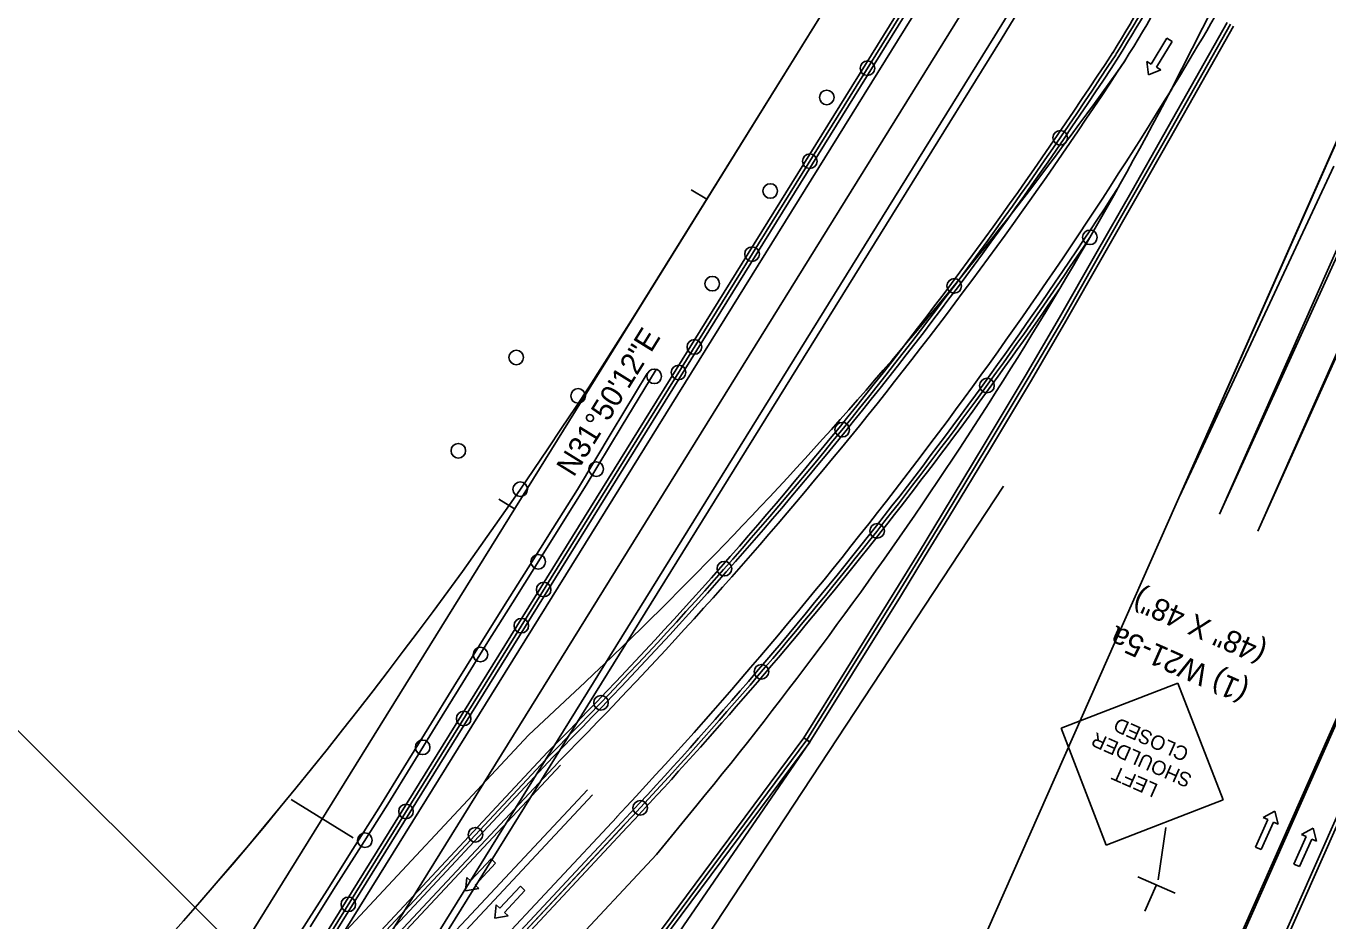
# Model space of a CAD drawing. Extents: x 659657 to 668193, y 633084 to 648639.
# Drawn here: x 662117 to 662474.2, y 643133.4 to 643378.9 of the extents above; entities that cross this region are included whole.
import ezdxf

# ---------------------------------------------------------------- set-up
doc = ezdxf.new("R2010")
doc.units = 0
for name, color, linetype in [('R_Border Prem', 7, 'Continuous'), ('R_Draft', 7, 'Continuous'), ('R_MOT_Stage 1', 7, 'Continuous'), ('R_MOT_Stage 1_Striping', 7, 'Continuous'), ('R_MOT_Stage 2', 7, 'Continuous'), ('R_MOT_Stage 2_Striping', 7, 'Continuous'), ('R_MOT_Stage 3', 7, 'Continuous'), ('R_MOT_Stage 3_Striping', 7, 'Continuous'), ('R_MOT_Stage 3_Striping_PPM', 7, 'Continuous'), ('R_MOT_Stage 4', 7, 'Continuous'), ('R_MOT_Stage 4_Striping', 7, 'Continuous'), ('R_MOT_Stage 4_Striping_PPM', 7, 'Continuous'), ('R_MOT_Stage 5_Striping_PPM', 7, 'Continuous'), ('R_ROW Annot', 7, 'Continuous'), ('S_EXISTING_ALIGNMENT', 7, 'Continuous'), ('T_Notes', 7, 'Continuous'), ('T_SIGNAL CONTROL CABINET', 7, 'Continuous'), ('TEMP_SIGNAL_POLES_STAGE 2', 7, 'Continuous')]:
    doc.layers.add(name, color=color, linetype=linetype)

msp = doc.modelspace()

# ---------------------------------------------------------------- linework, layer by layer
at = {"layer": 'R_Border Prem'}
msp.add_line((661686.79, 641562.92), (662861.91, 644217.67), dxfattribs=at)
at = {"layer": 'R_Draft'}
for p, q in [((662400.98, 643186.24), (662433.05, 643198.61)), ((662433.05, 643198.61), (662445.45, 643166.55)), ((662400.98, 643186.24), (662413.37, 643154.16)), ((662413.37, 643154.16), (662445.45, 643166.55)), ((662429.73, 643159.02), (662427.6, 643144.65)), ((662422.04, 643145.5), (662432.33, 643140.95)), ((662427.09, 643143.08), (662423.98, 643136.06))]:
    msp.add_line(p, q, dxfattribs=at)
at = {"layer": 'R_MOT_Stage 1'}
for centre in [(662336.72, 643359.32), (662321.21, 643333.64), (662305.3, 643308.21), (662289.38, 643282.78), (662273.46, 643257.35), (662257.54, 643231.92), (662241.69, 643206.45), (662225.83, 643180.99), (662209.98, 643155.52)]:
    msp.add_circle(centre, 2, dxfattribs=at)
at = {"layer": 'R_MOT_Stage 1_Striping'}
msp.add_line((662175.55, 643124.86), (662368.1, 643434.97), dxfattribs=at)
for points in [[(662299.52, 643334), (662303.77, 643331.36)], [(662175.55, 643124.86), (662034.06, 643266.21)], [(662246.77, 643249.05), (662251.02, 643246.41)], [(662189.77, 643166.73), (662206.77, 643156.18)]]:
    msp.add_lwpolyline(points, dxfattribs=at)
at = {"layer": 'R_MOT_Stage 2'}
for p, q in [((662183.21, 643104.02), (662360.74, 643389.94)), ((662184.91, 643102.96), (662362.44, 643388.89)), ((662206.99, 643089.25), (662384.53, 643375.17))]:
    msp.add_line(p, q, dxfattribs=at)
for centre in [(662347.86, 643367.31), (662332.04, 643341.82), (662316.21, 643316.33), (662300.39, 643290.85), (662251.51, 643287.96), (662296.04, 643283.85), (662268.5, 643277.41), (662235.62, 643262.37), (662252.61, 643251.82), (662259.05, 643224.28), (662252.91, 643214.39), (662237.09, 643188.9), (662221.26, 643163.41), (662205.44, 643137.93)]:
    msp.add_circle(centre, 2, dxfattribs=at)
msp.add_arc((661886.73, 643684.27), 585.96, 328.16324, 359.34796, dxfattribs=at)
at = {"layer": 'R_MOT_Stage 2_Striping'}
for p, q in [((662653.91, 643589.66), (661803.9, 641669.37)), ((661813.96, 641664.92), (662663.97, 643585.2)), ((662175.55, 643124.86), (662368.1, 643434.97)), ((662186.61, 643101.91), (662364.14, 643387.83)), ((662195.95, 643096.11), (662373.49, 643382.03)), ((662205.3, 643090.3), (662382.83, 643376.23))]:
    msp.add_line(p, q, dxfattribs=at)
for points in [[(662299.52, 643334), (662303.77, 643331.36)], [(662175.55, 643124.86), (662034.06, 643266.21)], [(662246.77, 643249.05), (662251.02, 643246.41)], [(662189.77, 643166.73), (662206.77, 643156.18)]]:
    msp.add_lwpolyline(points, dxfattribs=at)
msp.add_arc((661886.73, 643684.27), 583.96, 328.16324, 359.34796, dxfattribs=at)
at = {"layer": 'R_MOT_Stage 3'}
for p, q in [((662448.32, 643378.9), (662439.62, 643363.54)), ((662439.62, 643363.54), (662430.93, 643348.18)), ((662430.93, 643348.18), (662422.23, 643332.82)), ((662422.23, 643332.82), (662412.27, 643315.37)), ((662412.27, 643315.37), (662402.3, 643297.92)), ((662402.3, 643297.92), (662392.87, 643281.78)), ((662392.87, 643281.78), (662381.6, 643263.03)), ((662381.6, 643263.03), (662370.18, 643244.12)), ((662370.18, 643244.12), (662363.55, 643233.27)), ((662363.55, 643233.27), (662356.91, 643222.41)), ((662356.91, 643222.41), (662343.73, 643201.23)), ((662343.73, 643201.23), (662332.08, 643182.52)), ((662330.39, 643183.58), (662332.08, 643182.52))]:
    msp.add_line(p, q, dxfattribs=at)
for points in [[(662446.58, 643379.89), (662437.88, 643364.53), (662429.19, 643349.17), (662420.49, 643333.81), (662410.53, 643316.36), (662400.57, 643298.92), (662391.15, 643282.8), (662379.89, 643264.06), (662368.47, 643245.16), (662361.84, 643234.31), (662355.21, 643223.46), (662342.03, 643202.29), (662330.39, 643183.58)], [(662270.77, 643103.3), (662330.43, 643183.64)], [(662330.43, 643183.64), (662332.04, 643182.45)], [(662332.04, 643182.45), (662272.37, 643102.11)]]:
    msp.add_lwpolyline(points, dxfattribs=at)
at = {"layer": 'R_MOT_Stage 3_Striping'}
msp.add_lwpolyline([(662275.33, 643099.91), (662332.08, 643182.52), (662343.73, 643201.23), (662356.91, 643222.41), (662363.55, 643233.27), (662370.18, 643244.12), (662381.6, 643263.03), (662392.87, 643281.78), (662402.3, 643297.92), (662412.27, 643315.37), (662422.23, 643332.82), (662430.93, 643348.18), (662439.62, 643363.54), (662448.32, 643378.9)], dxfattribs=at)
at = {"layer": 'R_MOT_Stage 3_Striping_PPM'}
for p, q in [((661859, 641792.62), (662694.85, 643680.89)), ((661869.52, 641787.96), (662705.36, 643676.24)), ((662286.16, 643303), (662368.08, 643434.94))]:
    msp.add_line(p, q, dxfattribs=at)
msp.add_arc((661204.47, 643974.64), 1273.24, 308.51959, 328.16324, dxfattribs=at)
at = {"layer": 'R_MOT_Stage 4'}
for p, q in [((662123.59, 643033.62), (662260.12, 643179.66)), ((662125.01, 643032.2), (662261.56, 643178.27)), ((662040.8, 642904.05), (662280.53, 643160.49)), ((662042.22, 642902.64), (662281.99, 643159.13))]:
    msp.add_line(p, q, dxfattribs=at)
for centre in [(662400.77, 643348.25), (662408.91, 643320.93), (662371.68, 643307.59), (662380.66, 643280.27), (662340.95, 643268.16), (662350.52, 643240.38), (662308.62, 643230.02), (662318.8, 643201.74), (662274.76, 643193.24), (662285.54, 643164.4), (662240.32, 643157.02)]:
    msp.add_circle(centre, 2, dxfattribs=at)
for centre, radius, start, end in [((661447.27, 643963.26), 1134.42, 328.56301, 330.41188), ((661447.27, 643963.26), 1136.42, 328.56153, 330.41509), ((661395.1, 644037.06), 1217.94, 315.25335, 326.88093), ((661395.1, 644037.06), 1219.94, 315.25472, 326.88231), ((661374.24, 644009.51), 1241.85, 316.86861, 327.07813), ((661374.24, 644009.51), 1243.85, 316.86861, 325.6234)]:
    msp.add_arc(centre, radius, start, end, dxfattribs=at)
at = {"layer": 'R_MOT_Stage 4_Striping'}
for p, q in [((662475.79, 643340.42), (662433.48, 643249.79)), ((662485.93, 643336.15), (662444.46, 643244.94)), ((662495.91, 643331.52), (662454.97, 643240.28)), ((662031.56, 642913.21), (662271.03, 643169.37)), ((662039.38, 642905.46), (662279.07, 643161.86))]:
    msp.add_line(p, q, dxfattribs=at)
for points in [[(662431.31, 643361.56), (662454.07, 643406.49), (662628.36, 643713.48)], [(662015.94, 642928.72), (662126.42, 643030.78), (662263, 643176.88)]]:
    msp.add_lwpolyline(points, dxfattribs=at)
for centre, radius, start, end in [((661395.1, 644037.06), 1221.94, 315.25608, 326.8837), ((661374.24, 644009.51), 1239.85, 316.86861, 328.49623)]:
    msp.add_arc(centre, radius, start, end, dxfattribs=at)
at = {"layer": 'R_MOT_Stage 4_Striping_PPM'}
for p, q in [((661859, 641792.62), (662694.85, 643680.89)), ((661869.52, 641787.96), (662705.36, 643676.24)), ((662286.14, 643303.01), (662368.06, 643434.95))]:
    msp.add_line(p, q, dxfattribs=at)
for centre, radius, start, end in [((661447.27, 643963.26), 1138.42, 328.55574, 330.41509), ((661204.46, 643974.64), 1273.24, 308.51959, 328.16324)]:
    msp.add_arc(centre, radius, start, end, dxfattribs=at)
at = {"layer": 'R_MOT_Stage 5_Striping_PPM'}
for p, q in [((662444.46, 643244.94), (662727.79, 643885.03)), ((662454.97, 643240.28), (662738.31, 643880.37)), ((661859, 641792.62), (662694.85, 643680.89)), ((661869.52, 641787.96), (662705.36, 643676.24)), ((662433.48, 643249.79), (662518.92, 643442.81)), ((662286.16, 643303), (662368.08, 643434.94)), ((662254.92, 643184.34), (662267.67, 643196.3)), ((662015.9, 642928.67), (662254.92, 643184.34)), ((662024.66, 642920.47), (662263.68, 643176.15)), ((662033.43, 642912.28), (662272.45, 643167.95)), ((662289.98, 643151.56), (662301.06, 643165.1)), ((662042.19, 642904.08), (662281.21, 643159.76)), ((662050.96, 642895.89), (662289.98, 643151.56))]:
    msp.add_line(p, q, dxfattribs=at)
for centre, radius, start, end in [((661447.27, 643963.26), 1138.42, 328.55574, 330.41509), ((661447.27, 643963.26), 1153.42, 328.55574, 330.41509), ((661493.15, 644023.55), 1133.24, 313.11471, 324.74233), ((661401.42, 643902.96), 1163.52, 320.64225, 332.26987), ((661204.47, 643974.64), 1273.24, 308.51959, 328.16324)]:
    msp.add_arc(centre, radius, start, end, dxfattribs=at)
at = {"layer": 'R_ROW Annot'}
for p, q in [((662400.98, 643186.24), (662433.05, 643198.61)), ((662433.05, 643198.61), (662445.45, 643166.55)), ((662400.98, 643186.24), (662413.37, 643154.16)), ((662413.37, 643154.16), (662445.45, 643166.55)), ((662429.73, 643159.02), (662427.6, 643144.65)), ((662422.04, 643145.5), (662432.33, 643140.95)), ((662427.09, 643143.08), (662423.98, 643136.06))]:
    msp.add_line(p, q, dxfattribs=at)
at = {"layer": 'S_EXISTING_ALIGNMENT'}
msp.add_line((662385.21, 643252.62), (662254.78, 643054.55), dxfattribs=at)
at = {"layer": 'T_Notes'}
for p, q in [((662400.98, 643186.24), (662433.05, 643198.61)), ((662433.05, 643198.61), (662445.45, 643166.55)), ((662400.98, 643186.24), (662413.37, 643154.16)), ((662413.37, 643154.16), (662445.45, 643166.55)), ((662429.73, 643159.02), (662427.6, 643144.65)), ((662422.04, 643145.5), (662432.33, 643140.95)), ((662427.09, 643143.08), (662423.98, 643136.06))]:
    msp.add_line(p, q, dxfattribs=at)
at = {"layer": 'T_SIGNAL CONTROL CABINET'}
for p, q in [((662361.59, 643389.42), (662184.06, 643103.49)), ((662425.73, 643368.47), (662430.01, 643375.55)), ((662427.18, 643367.6), (662431.45, 643374.68)), ((662431.45, 643374.68), (662430.01, 643375.55)), ((662425.73, 643368.47), (662424.53, 643369.2)), ((662424.95, 643365.53), (662424.53, 643369.2)), ((662428.38, 643366.87), (662424.95, 643365.53)), ((662428.38, 643366.87), (662427.18, 643367.6)), ((662271.57, 643102.7), (662331.23, 643183.05)), ((662021.56, 642923.02), (662260.84, 643178.96)), ((662456.43, 643161.75), (662459.67, 643163.51)), ((662456.43, 643161.75), (662459.67, 643163.51)), ((662459.67, 643163.51), (662460.55, 643159.92)), ((662459.67, 643163.51), (662460.55, 643159.92)), ((662041.51, 642903.35), (662281.26, 643159.81)), ((662457.72, 643161.18), (662454.37, 643153.61)), ((662457.72, 643161.18), (662454.37, 643153.61)), ((662459.26, 643160.49), (662455.91, 643152.93)), ((662459.26, 643160.49), (662455.91, 643152.93)), ((662456.43, 643161.75), (662457.72, 643161.18)), ((662456.43, 643161.75), (662457.72, 643161.18)), ((662459.26, 643160.49), (662460.55, 643159.92)), ((662459.26, 643160.49), (662460.55, 643159.92)), ((662466.94, 643157.08), (662470.18, 643158.84)), ((662466.94, 643157.08), (662470.18, 643158.84)), ((662470.18, 643158.84), (662471.06, 643155.25)), ((662470.18, 643158.84), (662471.06, 643155.25)), ((662468.23, 643156.51), (662464.88, 643148.94)), ((662468.23, 643156.51), (662464.88, 643148.94)), ((662469.77, 643155.82), (662466.42, 643148.26)), ((662469.77, 643155.82), (662466.42, 643148.26)), ((662466.94, 643157.08), (662468.23, 643156.51)), ((662466.94, 643157.08), (662468.23, 643156.51)), ((662469.77, 643155.82), (662471.06, 643155.25)), ((662469.77, 643155.82), (662471.06, 643155.25)), ((662454.37, 643153.61), (662455.91, 643152.93)), ((662454.37, 643153.61), (662455.91, 643152.93)), ((662238.98, 643144.37), (662244.63, 643150.42)), ((662240.21, 643143.22), (662245.86, 643149.26)), ((662245.86, 643149.26), (662244.63, 643150.42)), ((662464.88, 643148.94), (662466.42, 643148.26)), ((662464.88, 643148.94), (662466.42, 643148.26)), ((662237.6, 643141.66), (662237.95, 643145.33)), ((662238.98, 643144.37), (662237.95, 643145.33)), ((662241.24, 643142.26), (662237.6, 643141.66)), ((662241.24, 643142.26), (662240.21, 643143.22)), ((662247.01, 643136.86), (662252.67, 643142.9)), ((662248.25, 643135.71), (662253.9, 643141.75)), ((662253.9, 643141.75), (662252.67, 643142.9)), ((662245.64, 643134.15), (662245.99, 643137.82)), ((662247.01, 643136.86), (662245.99, 643137.82)), ((662249.27, 643134.75), (662245.64, 643134.15)), ((662249.27, 643134.75), (662248.25, 643135.71))]:
    msp.add_line(p, q, dxfattribs=at)
msp.add_lwpolyline([(662331.23, 643183.05), (662342.88, 643201.76), (662356.06, 643222.94), (662362.7, 643233.79), (662369.33, 643244.64), (662380.74, 643263.54), (662392.01, 643282.29), (662401.44, 643298.42), (662411.4, 643315.87), (662421.36, 643333.31), (662430.06, 643348.67), (662438.75, 643364.03), (662447.45, 643379.39)], dxfattribs=at)
for centre, radius, start, end in [((661447.27, 643963.26), 1135.42, 328.56301, 330.41188), ((661395.1, 644037.06), 1218.94, 315.25404, 326.8788), ((661374.24, 644009.51), 1242.85, 316.86861, 326.35559)]:
    msp.add_arc(centre, radius, start, end, dxfattribs=at)
at = {"layer": 'TEMP_SIGNAL_POLES_STAGE 2'}
for points in [[(662194.98, 643131.73), (662202.06, 643142.96), (662209.15, 643154.2), (662216.24, 643165.44), (662223.12, 643176.57), (662229.99, 643187.69), (662236.86, 643198.82), (662243.73, 643209.93), (662250.47, 643220.66), (662257.22, 643231.4), (662263.96, 643242.14), (662270.71, 643252.89), (662280.32, 643268.81), (662289.91, 643284.71)], [(662192.55, 643130.62), (662199.64, 643141.85), (662206.72, 643153.09), (662213.81, 643164.32), (662220.68, 643175.44), (662227.55, 643186.57), (662234.42, 643197.69), (662241.3, 643208.81), (662248.04, 643219.55), (662254.79, 643230.29), (662261.53, 643241.02), (662268.28, 643251.76), (662277.87, 643267.66), (662287.47, 643283.56)]]:
    msp.add_lwpolyline(points, dxfattribs=at)

# ---------------------------------------------------------------- texts
at = {"layer": 'R_Draft'}
for s, height, rotation, p in [('(48" X 48")', 6, 156.1234, (662457.8, 643208.92)), ('(1) W21-5a', 6, 156.1234, (662452.9, 643198.25)), ('CLOSED', 3.94, 156.122, (662436.39, 643180.53)), ('SHOULDER', 3.94, 156.122, (662437.22, 643173.38)), ('LEFT', 3.94, 156.1224, (662427.88, 643170.74))]:
    msp.add_text(s, height=height, rotation=rotation, dxfattribs=at).set_placement(p)
at = {"layer": 'R_MOT_Stage 1_Striping'}
msp.add_text('N31%%d50\'12"E', height=6, rotation=58.1632, dxfattribs=at).set_placement((662267.28, 643254.92))
at = {"layer": 'R_MOT_Stage 2_Striping'}
msp.add_text('N31%%d50\'12"E', height=6, rotation=58.1632, dxfattribs=at).set_placement((662267.28, 643254.92))
at = {"layer": 'R_ROW Annot'}
for s, height, rotation, p in [('(48" X 48")', 6, 156.1234, (662457.8, 643208.92)), ('(1) W21-5a', 6, 156.1234, (662452.9, 643198.25)), ('CLOSED', 3.94, 156.122, (662436.39, 643180.53)), ('SHOULDER', 3.94, 156.122, (662437.22, 643173.38)), ('LEFT', 3.94, 156.1224, (662427.88, 643170.74))]:
    msp.add_text(s, height=height, rotation=rotation, dxfattribs=at).set_placement(p)
at = {"layer": 'T_Notes'}
for s, height, rotation, p in [('(48" X 48")', 6, 156.1234, (662457.8, 643208.92)), ('(1) W21-5a', 6, 156.1234, (662452.9, 643198.25)), ('CLOSED', 3.94, 156.122, (662436.39, 643180.53)), ('SHOULDER', 3.94, 156.122, (662437.22, 643173.38)), ('LEFT', 3.94, 156.1224, (662427.88, 643170.74))]:
    msp.add_text(s, height=height, rotation=rotation, dxfattribs=at).set_placement(p)

doc.saveas('drawing.dxf')
